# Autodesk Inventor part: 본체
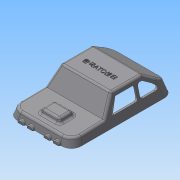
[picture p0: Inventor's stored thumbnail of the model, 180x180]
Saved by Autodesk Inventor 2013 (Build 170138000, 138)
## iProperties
Created: 2015-05
Part Number: 본체
Material: 일반
Document SubType Name: Modeling
Designer: dgall
Density: 1 g/cm^3
Author: dgall
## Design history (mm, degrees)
sketch "스케치1"
  geometry: L1 (-61, 0)-(-58.588, 9); L2 (-58.588, 9)-(-19, 10); L3 (-19, 10)-(-5.736, 30); L4 (-5.736, 30)-(31, 30); L5 (31, 30)-(61, 10); L6 (61, 10)-(61, 0); L7 (61, 0)-(-61, 0); 2 further points
  constraints: 14 end point, 1 coincident, 1 horizontal, 1 midpoint, 1 parallel, 1 vertical
  dimensions: "d0" = 122 distance of L6.end L1.start; "d1" = 9 vertical distance of L1.start L1.end; "d2" = 42 horizontal distance of L2.end L1.start; "d3" = 105 deg angle of L1 L7; "d4" = 30 distance between parallel lines of L7 L4; "d7" = 125 deg angle of L3 L2; "d8" = 20 vertical distance of L2.end L3.end; "d29" = 30 horizontal distance of L6.end L4.end; "d30" = 20 vertical distance of L5.end L4.end
extrude "돌출1" new body sketch "스케치1" stored distance "d10" = 76; taper "d11" = 0 deg
node "작업 평면1"
sketch "스케치2"
  geometry: L1 (38, 10)-(38, 30) reference; L2 (38, 9)-(38, 10) reference; L3 (38, 0)-(38, 9) reference; L4 (38, 0)-(-38, 0) reference; L5 (-38, 30)-(38, 30) reference; L6 (38, 0)-(29.962, 30); L7 (38, 0)-(38, 30); L8 (29.962, 30)-(38, 30); 1 further point
  constraints: 6 end point, 1 collinear, 1 perpendicular, 1 point on line
  dimensions: "d13" = 105 deg angle of L4 L6
extrude "돌출2" cut sketch "스케치2" distance "d14" = 150; taper "d15" = 0 deg
node "작업 평면2"
sketch "스케치4"
  geometry: L1 (61, 10)-(61, 0) reference; L2 (-61, 0)-(61, 0) reference; L3 (31, 30)-(61, 10) reference; L4 (61, 0)-(57.738, 12.175); L5 (57.738, 12.175)-(61, 10); L6 (61, 0)-(61, 10); 1 further point
  constraints: 6 end point, 1 collinear, 1 perpendicular, 1 point on line
  dimensions: "d32" = 105 deg angle of L4 L2
extrude "돌출3" cut sketch "스케치4" distance "d33" = 150; taper "d34" = 0 deg
feature "쉘2" dims "d35" = 2
sketch "스케치6"
  geometry: L1 (-5.736, 30)-(31, 30) reference; L2 (-19, 10)-(-5.736, 30) reference; L3 (31, 30)-(57.738, 12.175) reference; L4 (61, 0)-(57.738, 12.175) reference; L5 (-3.052, 25)-(-13, 10); L6 (-3.052, 25)-(21, 25); L7 (21, 25)-(21, 10); L8 (21, 10)-(-13, 10); L9 (29.486, 25)-(51.986, 10); L10 (29.486, 25)-(23.986, 25); L11 (23.986, 25)-(23.986, 10); L12 (23.986, 10)-(51.986, 10); 1 further point
  constraints: 16 end point, 6 parallel, 2 perpendicular
  dimensions: "d46" = 5 distance between parallel lines of L2 L5; "d48" = 5 distance between parallel lines of L1 L6; "d49" = 34 distance of L7.end L5.end; "d50" = 15 distance of L6.end L7.end; "d51" = 5 distance between parallel lines of L3 L9; "d52" = 5 distance from line of L1 L9.start; "d53" = 15 vertical distance of L9.start L9.end; "d54" = 28 distance of L11.end L9.end
extrude "돌출4" cut sketch "스케치6" distance "d55" = 150; taper "d56" = 0 deg
sketch "스케치8"
  geometry: L1 (0, 0)-(68.087, 0) reference; L2 (21.044, 26.867)-(47.044, 26.867); L3 (47.044, 26.867)-(47.044, 6.867); L4 (47.044, 6.867)-(21.044, 6.867); L5 (21.044, 6.867)-(21.044, 26.867); L6 (72.044, -4.133)-(-3.956, -4.133) reference; 3 further points
  constraints: 8 end point, 2 midpoint, 2 parallel, 1 horizontal, 1 perpendicular, 1 vertical alignment
  dimensions: "d63" = 26 distance of L2.start L2.end; "d65" = 20 distance of L2.end L3.end; "d66" = 11 distance between parallel lines of L4 L6
extrude "돌출6" join sketch "스케치8" distance "d67" = 7; taper "d68" = -20 deg
sketch "스케치9"
  geometry: L1 (21.044, 26.867)-(47.044, 26.867) reference; L2 (21.044, 6.867)-(21.044, 26.867) reference; L3 (47.044, 6.867)-(21.044, 6.867) reference; L4 (47.044, 26.867)-(47.044, 6.867) reference; L5 (45.044, 24.867)-(23.044, 24.867); L6 (23.044, 24.867)-(23.044, 8.867); L7 (23.044, 8.867)-(45.044, 8.867); L8 (45.044, 8.867)-(45.044, 24.867); 1 further point
  constraints: 8 end point, 3 other
  dimensions: "d69" = 2 distance between parallel lines of L1 L5
extrude "돌출7" cut sketch "스케치9" distance "d70" = 5; taper "d71" = -20 deg
fillet "모깎기1" dims "d72" = 12
fillet "모깎기2" dims "d73" = 12
fillet "모깎기3" dims "d74" = 3
fillet "모깎기4" dims "d75" = 3
fillet "모깎기5" dims "d76" = 3
fillet "모깎기6" dims "d77" = 3
sketch "스케치10"
  geometry: L1 (2.071, 119.929)-(50.747, 119.929) reference; L2 (62.338, 108.338)-(62.338, 13.662) reference; L3 (50.747, 2.071)-(2.071, 2.071) reference; L4 (-9.521, 13.662)-(-9.521, 108.338) reference; L5 (50.747, 120.929)-(2.071, 120.929); L6 (-10.521, 108.338)-(-10.521, 13.662); L7 (2.071, 1.071)-(50.747, 1.071); L8 (63.338, 13.662)-(63.338, 108.338); 5 further points; 4 other entities
  constraints: 8 end point, 7 parallel, 16 other
  dimensions: "d78" = 1 distance between parallel lines of L5 L1
extrude "돌출8" join sketch "스케치10" distance "d79" = 1; taper "d80" = 0 deg
fillet "모깎기7" dims "d81" = 3
sketch "스케치11"
  geometry: L1 (0, 122)-(52.818, 122) reference; C1 r 3 at (26.409, 21); 1 further point
  constraints: 1 centre point, 1 vertical alignment
  dimensions: "d82" = 6 diameter of C1; "d84" = 101 distance from line of L1 C1.centre
extrude "돌출9" join sketch "스케치11" stored distance "d85" = 1; taper "d86" = 2 deg
sketch "스케치12"
  geometry: L1 (-28.863, 9.751)-(-19, 10) reference; L2 (-19, 10)-(-6.626, 28.658) reference; L3 (-4.125, 30)-(30.092, 30) reference; L4 (31.756, 29.496)-(56.797, 12.802) reference; L5 (58.03, 11.082)-(61, 0) reference; L6 (61, 0)-(59.929, 0) reference; L7 (59.929, 0)-(59.929, -1) reference; L8 (59.929, -1)-(58.929, -1) reference; L9 (58.929, -1)-(58.929, 0) reference; L10 (58.929, 0)-(56.294, 9.837) reference; L11 (55.06, 11.556)-(31.15, 27.496) reference; L12 (29.486, 28)-(-3.052, 28) reference; L13 (-5.552, 26.658)-(-17.046, 9.328) reference; L14 (-19.47, 7.987)-(-30.084, 7.719) reference; L15 (-32.952, 9.621)-(-33.362, 10.664) reference; L16 (-36.23, 12.566)-(-36.561, 12.557) reference; L17 (-36.561, 12.557)-(-37, 0) reference; L18 (-37, 0)-(-43, 0) reference; L19 (-43, 0)-(-43.432, 12.384) reference; L20 (-43.432, 12.384)-(-44.386, 12.36) reference; L21 (-47.155, 10.315)-(-47.511, 9.254) reference; L22 (-50.279, 7.209)-(-54.802, 7.095) reference; L23 (-57.624, 4.872)-(-58.929, 0) reference; L24 (-58.929, 0)-(-58.929, -1) reference; L25 (-58.929, -1)-(-59.929, -1) reference; L26 (-59.929, -1)-(-59.929, 0) reference; L27 (-59.929, 0)-(-61, 0) reference; L28 (-61, 0)-(-59.169, 6.834) reference; L29 (-56.347, 9.057)-(-51.601, 9.176) reference; L30 (-48.833, 11.221)-(-48.477, 12.282) reference; L31 (-45.708, 14.327)-(-35.009, 14.597) reference; L32 (-32.141, 12.695)-(-31.731, 11.653) reference; L33 (-42.07, 2)-(-42.07, 12.919); L34 (-46.925, 12.919)-(-45, 2); L35 (47.338, 0)-(-47.338, 0) reference; L36 (-37, 0)-(-43, 0) reference; L37 (-45, 2)-(-42.07, 2); L38 (-42.07, 12.919)-(-46.925, 12.919); A1 r 3 centre (-28.939, 12.75) between (-31.731, 11.653) and (-28.863, 9.751) reference; A2 r 3 centre (-4.125, 27) between (-4.125, 30) and (-6.626, 28.658) reference; A3 r 3 centre (30.092, 27) between (31.756, 29.496) and (30.092, 30) reference; A4 r 3 centre (55.133, 10.306) between (58.03, 11.082) and (56.797, 12.802) reference; A5 r 3 centre (53.396, 9.06) between (56.294, 9.837) and (55.06, 11.556) reference; A6 r 3 centre (29.486, 25) between (31.15, 27.496) and (29.486, 28) reference; A7 r 3 centre (-3.052, 25) between (-3.052, 28) and (-5.552, 26.658) reference; A8 r 3 centre (-19.546, 10.987) between (-19.47, 7.987) and (-17.046, 9.328) reference; A9 r 3 centre (-30.16, 10.718) between (-32.952, 9.621) and (-30.084, 7.719) reference; A10 r 3 centre (-36.154, 9.567) between (-33.362, 10.664) and (-36.23, 12.566) reference; A11 r 3 centre (-44.311, 9.361) between (-44.386, 12.36) and (-47.155, 10.315) reference; A12 r 3 centre (-50.355, 10.208) between (-50.279, 7.209) and (-47.511, 9.254) reference; A13 r 3 centre (-54.726, 4.096) between (-54.802, 7.095) and (-57.624, 4.872) reference; A14 r 3 centre (-56.271, 6.058) between (-56.347, 9.057) and (-59.169, 6.834) reference; A15 r 3 centre (-51.677, 12.176) between (-51.601, 9.176) and (-48.833, 11.221) reference; A16 r 3 centre (-45.633, 11.328) between (-45.708, 14.327) and (-48.477, 12.282) reference; A17 r 3 centre (-34.933, 11.598) between (-32.141, 12.695) and (-35.009, 14.597) reference; 3 further points
  constraints: 8 end point, 2 parallel, 1 midpoint, 1 perpendicular, 1 point on circle, 1 point on line
  dimensions: "d90" = 10 deg angle of L33 L34; "d110" = 5 horizontal distance of point (-40, 0) L34.end; "d112" = 2.06984 distance from line of point (-40, 0) L33; "d114" = 2 distance between parallel lines of L35 L37; "d115" = 12.91909 distance between parallel lines of L36 L38
extrude "돌출10" join sketch "스케치12" stored distance "d92" = 2; taper "d93" = 0 deg
node "작업 평면3"
hole "구멍1" diameter "d97" = 3.242; stored, may be unused: countersink angle "d101" = 90 deg, drill point angle "d103" = 118 deg; dims "d95" = 10, "d96" = 10, "d98" = 9, "d99" = 4, "d100" = 2, "d102" = 11
sketch "스케치13"
  geometry: C1 r 3 at (26.409, 101); C2 r 1.621 at (26.409, 21) reference; 1 further point
  constraints: 1 centre point, 1 vertical alignment
  dimensions: "d104" = 6 diameter of C1; "d106" = 80 distance of C1.centre C2.centre
extrude "돌출11" join sketch "스케치13" stored distance "d107" = 2; taper "d108" = 2 deg
sketch "스케치14"
  geometry: L1 (-28.863, 9.751)-(-19, 10) reference; L2 (-19, 10)-(-6.626, 28.658) reference; L3 (-4.125, 30)-(30.092, 30) reference; L4 (31.756, 29.496)-(56.797, 12.802) reference; L5 (58.03, 11.082)-(61, 0) reference; L6 (61, 0)-(59.929, 0) reference; L7 (59.929, 0)-(59.929, -1) reference; L8 (59.929, -1)-(58.929, -1) reference; L9 (58.929, -1)-(58.929, 0) reference; L10 (58.929, 0)-(56.294, 9.837) reference; L11 (55.06, 11.556)-(43.669, 19.15) reference; L12 (43.669, 19.15)-(43, 0) reference; L13 (43, 0)-(37, 0) reference; L14 (37, 0)-(36.156, 24.159) reference; L15 (36.156, 24.159)-(31.15, 27.496) reference; L16 (29.486, 28)-(-3.052, 28) reference; L17 (-5.552, 26.658)-(-17.046, 9.328) reference; L18 (-19.47, 7.987)-(-30.084, 7.719) reference; L19 (-32.952, 9.621)-(-33.362, 10.664) reference; L20 (-33.44, 10.845)-(-35, 2) reference; L21 (-36.93, 2)-(-37, 0) reference; L22 (-37, 0)-(-38.379, 0) reference; L23 (-38.379, 0)-(-38.379, 11) reference; L24 (-38.379, 11)-(-40, 11.974) reference; L25 (-40, 11.974)-(-41.621, 11) reference; L26 (-41.621, 11)-(-41.621, 0) reference; L27 (-41.621, 0)-(-43, 0) reference; L28 (-43, 0)-(-43.07, 2) reference; L29 (-45, 2)-(-46.633, 11.26) reference; L30 (-47.155, 10.315)-(-47.511, 9.254) reference; L31 (-50.279, 7.209)-(-54.802, 7.095) reference; L32 (-57.624, 4.872)-(-58.929, 0) reference; L33 (-58.929, 0)-(-58.929, -1) reference; L34 (-58.929, -1)-(-59.929, -1) reference; L35 (-59.929, -1)-(-59.929, 0) reference; L36 (-59.929, 0)-(-61, 0) reference; L37 (-61, 0)-(-59.169, 6.834) reference; L38 (-56.347, 9.057)-(-51.601, 9.176) reference; L39 (-48.833, 11.221)-(-48.477, 12.282) reference; L40 (-45.708, 14.327)-(-35.009, 14.597) reference; L41 (-32.141, 12.695)-(-31.731, 11.653) reference; L42 (-35, 2)-(-36.93, 2) reference; L43 (-43.07, 2)-(-45, 2) reference; L44 (43, 0)-(46.092, 17.535); L45 (37, 0)-(32.285, 26.74); L46 (40, 0)-(40, 24); L47 (37, 0)-(38.023, 0); L48 (38.023, 0)-(38.023, 23.037); L49 (38.023, 23.037)-(36.156, 24.159); L50 (43, 0)-(42.333, 0); L51 (42.333, 0)-(42.333, 19.953); L52 (42.333, 19.953)-(43.669, 19.15); A1 r 3 centre (-28.939, 12.75) between (-31.731, 11.653) and (-28.863, 9.751) reference; A2 r 3 centre (-4.125, 27) between (-4.125, 30) and (-6.626, 28.658) reference; A3 r 3 centre (30.092, 27) between (31.756, 29.496) and (30.092, 30) reference; A4 r 3 centre (55.133, 10.306) between (58.03, 11.082) and (56.797, 12.802) reference; A5 r 3 centre (53.396, 9.06) between (56.294, 9.837) and (55.06, 11.556) reference; A6 r 3 centre (29.486, 25) between (31.15, 27.496) and (29.486, 28) reference; A7 r 3 centre (-3.052, 25) between (-3.052, 28) and (-5.552, 26.658) reference; A8 r 3 centre (-19.546, 10.987) between (-19.47, 7.987) and (-17.046, 9.328) reference; A9 r 3 centre (-30.16, 10.718) between (-32.952, 9.621) and (-30.084, 7.719) reference; A10 r 3 centre (-36.154, 9.567) between (-33.362, 10.664) and (-33.44, 10.845) reference; A11 r 3 centre (-44.311, 9.361) between (-46.633, 11.26) and (-47.155, 10.315) reference; A12 r 3 centre (-50.355, 10.208) between (-50.279, 7.209) and (-47.511, 9.254) reference; A13 r 3 centre (-54.726, 4.096) between (-54.802, 7.095) and (-57.624, 4.872) reference; A14 r 3 centre (-56.271, 6.058) between (-56.347, 9.057) and (-59.169, 6.834) reference; A15 r 3 centre (-51.677, 12.176) between (-51.601, 9.176) and (-48.833, 11.221) reference; A16 r 3 centre (-45.633, 11.328) between (-45.708, 14.327) and (-48.477, 12.282) reference; A17 r 3 centre (-34.933, 11.598) between (-32.141, 12.695) and (-35.009, 14.597) reference; 1 further point
  constraints: 18 end point, 5 point on line, 3 perpendicular, 2 parallel, 1 midpoint
  dimensions: "d116" = 10 deg angle of L46 L45; "d117" = 10 deg angle of L46 L44
extrude "돌출12" join sketch "스케치14" stored distance "d118" = 2; taper "d119" = 0 deg
hole "구멍2" diameter "d122" = 3.242; stored, may be unused: countersink angle "d126" = 90 deg, drill point angle "d128" = 118 deg; dims "d120" = 10, "d121" = 10, "d123" = 9, "d124" = 4, "d125" = 2, "d127" = 11
sketch "스케치15"
  geometry: C1 r 3 at (48.12, 61.012); C2 r 1.621 at (26.12, 101.012) reference; 1 further point
  constraints: 1 centre point
  dimensions: "d129" = 6 diameter of C1; "d131" = 40 vertical distance of C2.centre C1.centre; "d132" = 22 horizontal distance of C2.centre C1.centre
extrude "돌출13" join sketch "스케치15" stored distance "d133" = 2; taper "d134" = 2 deg
node "작업 평면4"
sketch "스케치16"
  geometry: L1 (-56.347, 9.057)-(-19, 10) reference; L2 (-19, 10)-(-6.626, 28.658) reference; L3 (-4.125, 30)-(30.092, 30) reference; L4 (31.756, 29.496)-(56.797, 12.802) reference; L5 (58.03, 11.082)-(61, 0) reference; L6 (61, 0)-(59.929, 0) reference; L7 (59.929, 0)-(59.929, -1) reference; L8 (59.929, -1)-(58.929, -1) reference; L9 (58.929, -1)-(58.929, 0) reference; L10 (58.929, 0)-(56.591, 8.727) reference; L11 (55.054, 11.56)-(31.15, 27.496) reference; L12 (29.486, 28)-(3.979, 28) reference; L13 (2.998, 0)-(-2.974, 0) reference; L14 (-5.552, 26.658)-(-17.046, 9.328) reference; L15 (-19.47, 7.987)-(-54.802, 7.095) reference; L16 (-57.624, 4.872)-(-58.929, 0) reference; L17 (-58.929, 0)-(-58.929, -1) reference; L18 (-58.929, -1)-(-59.929, -1) reference; L19 (-59.929, -1)-(-59.929, 0) reference; L20 (-59.929, 0)-(-61, 0) reference; L21 (-61, 0)-(-59.169, 6.834) reference; L22 (-2.974, 0)-(-7.402, 25.113); L23 (2.998, 0)-(7.93, 27.969); L24 (0, 0)-(0, 30); L25 (-7.402, 25.113)-(-5.508, 27.969); L26 (-5.508, 27.969)-(-2, 27.969); L27 (-2.974, 0)-(-2, 0); L28 (-2, 0)-(-2, 28); L29 (2.998, 0)-(1.601, 0); L30 (1.601, 0)-(1.601, 27.969); L31 (1.601, 27.969)-(7.93, 27.969); A1 r 3 centre (-56.271, 6.058) between (-56.347, 9.057) and (-59.169, 6.834) reference; A2 r 3 centre (-4.125, 27) between (-4.125, 30) and (-6.626, 28.658) reference; A3 r 3 centre (30.092, 27) between (31.756, 29.496) and (30.092, 30) reference; A4 r 3 centre (55.133, 10.306) between (58.03, 11.082) and (56.797, 12.802) reference; A5 r 3 centre (29.486, 25) between (31.15, 27.496) and (29.486, 28) reference; A6 r 3 centre (-3.052, 25) between (-3.95, 27.862) and (-5.552, 26.658) reference; A7 r 3 centre (-19.546, 10.987) between (-19.47, 7.987) and (-17.046, 9.328) reference; A8 r 3 centre (-54.726, 4.096) between (-54.802, 7.095) and (-57.624, 4.872) reference; 2 further points; 1 other entity
  constraints: 20 end point, 5 perpendicular, 4 point on line, 2 parallel, 1 horizontal alignment, 4 other
  dimensions: "d136" = 10 deg angle of L24 L22; "d137" = 10 deg angle of L23 L24
extrude "돌출14" join sketch "스케치16" stored distance "d138" = 2; taper "d139" = 0 deg
hole "구멍3" diameter "d142" = 3.242; stored, may be unused: countersink angle "d146" = 90 deg, drill point angle "d148" = 118 deg; dims "d140" = 10, "d141" = 10, "d143" = 9, "d144" = 4, "d145" = 2, "d147" = 11
sketch "스케치18"
  geometry: L1 (54.068, 65.125)-(1.251, 65.125) reference; 3 further points
  constraints: 1 midpoint, 1 vertical alignment, 1 other
  dimensions: "d149" = 50 distance from line of L1 point (27.66, 15.125)
feature "엠보싱1" sketch "스케치18" dims "d150" = 0.5, "d151" = 0
node "작업 평면5"
sketch "스케치19"
  geometry: L1 (-2.071, 0)-(50.747, 0) reference; A1 r 4 centre (14.338, 0) between (18.338, 0) and (10.338, 0); A2 r 4 centre (3.338, 0) between (7.338, 0) and (-0.662, 0); 1 further point
  constraints: 4 point on circle, 4 point on line, 2 centre point, 2 horizontal alignment, 1 equal radius
  dimensions: "d155" = 8 diameter of A1; "d157" = 10 distance of point (24.338, 0) A1.centre; "d158" = 11 distance of A1.centre A2.centre
extrude "돌출15" join sketch "스케치19" stored distance "d159" = 2; taper "d160" = 0 deg
chamfer "모따기1" distance "d161" = 1; stored, may be unused: second distance "d162" = 2, angle "d163" = 45 deg
node "솔리드1"
mirror "대칭1"
mirror "대칭2"
mirror "대칭3"
mirror "대칭4"
node "절단 모서리 투영1"
node "절단 모서리 투영2"
node "절단 모서리 투영3"
other parameters: "d31" = 51.75, "d135" = -22, "d152" = 3
